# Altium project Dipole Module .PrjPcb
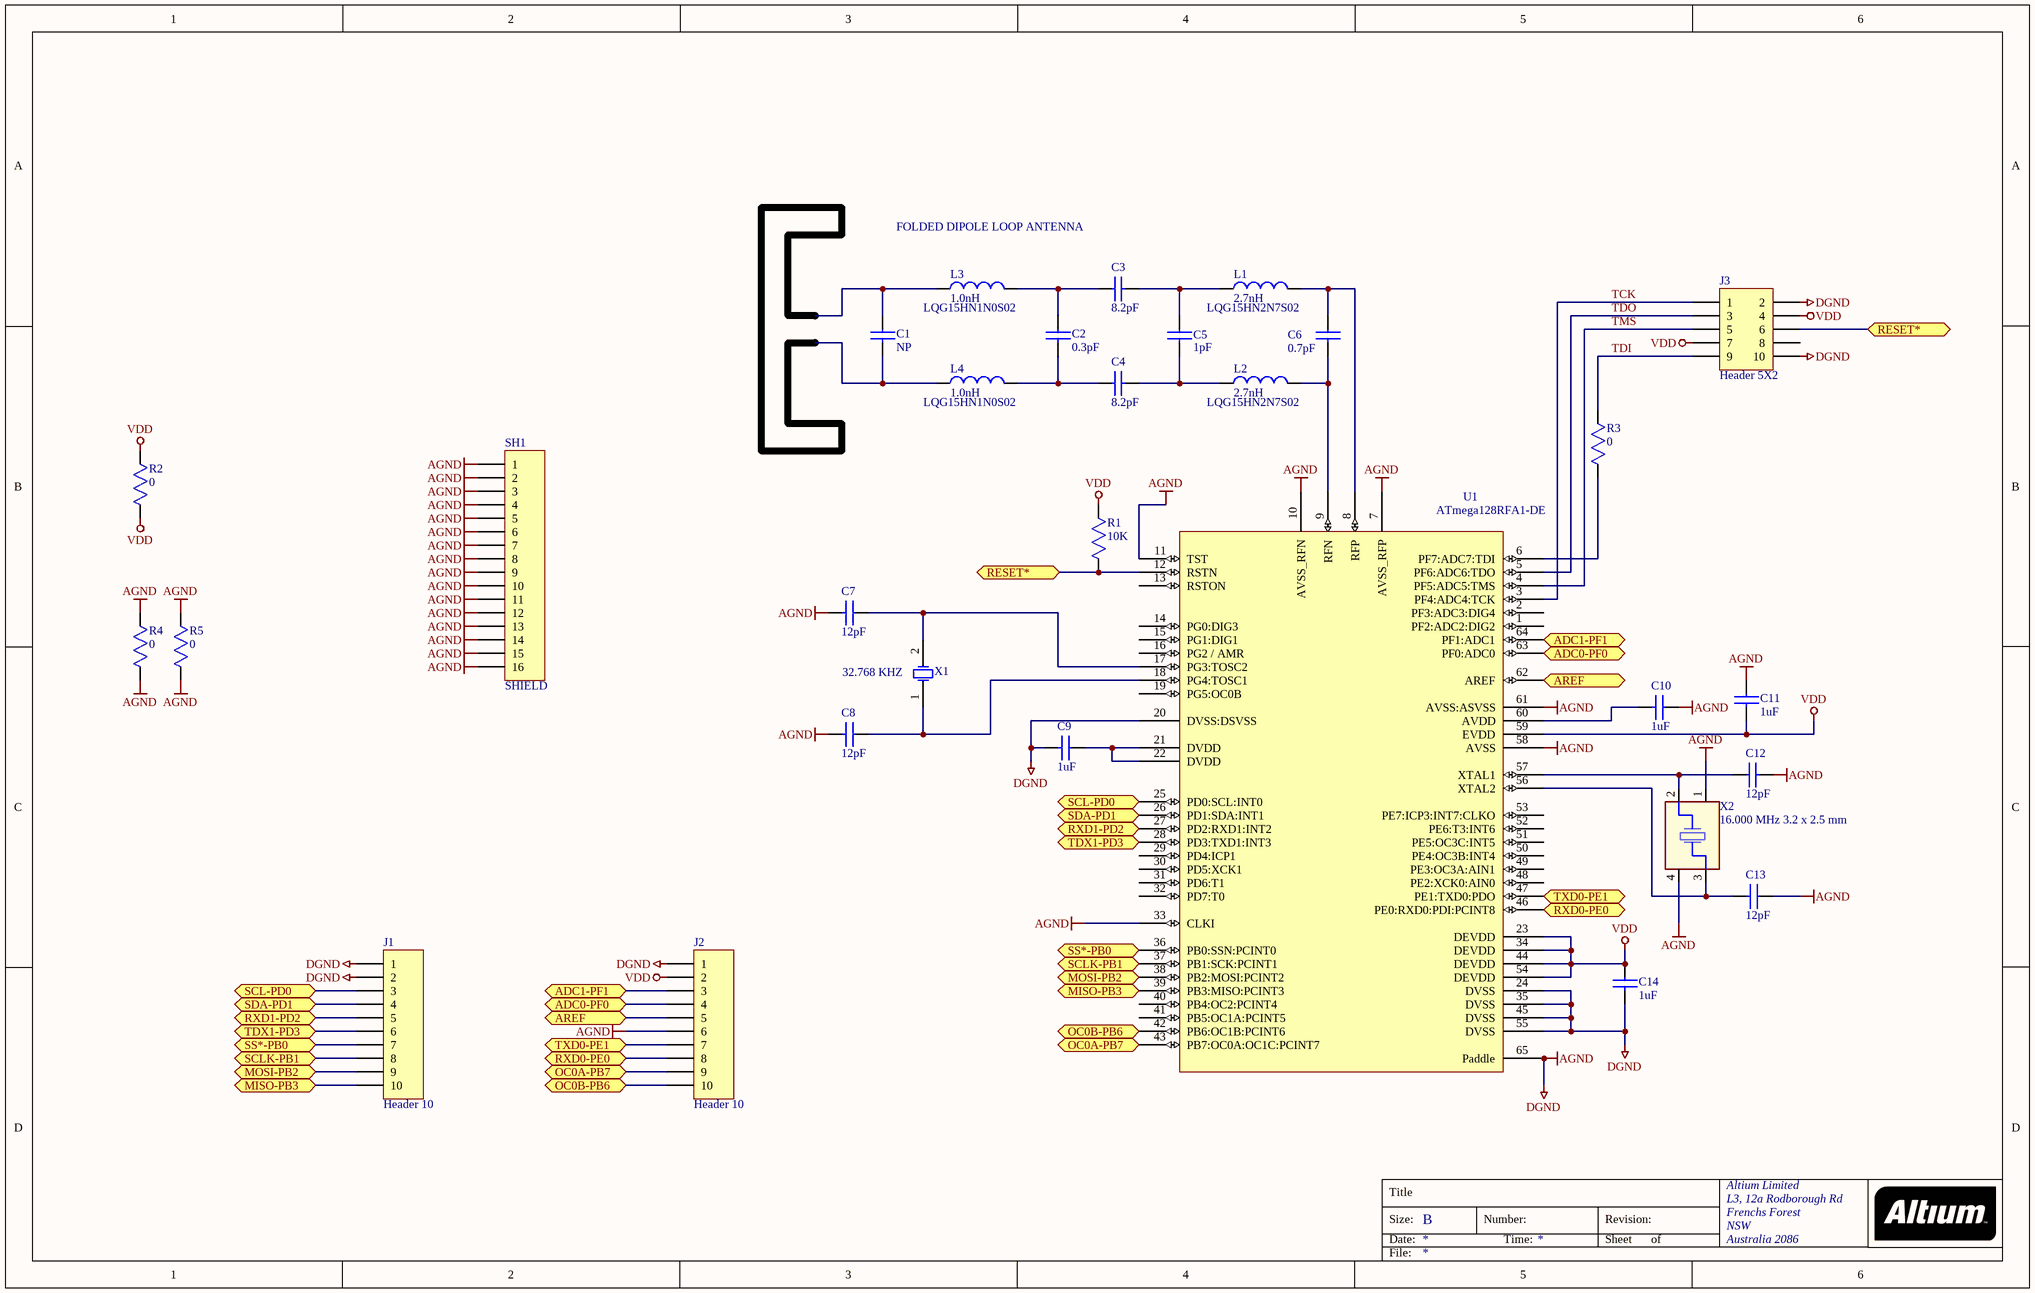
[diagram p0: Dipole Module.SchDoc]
1 sheet, 30 parts. Net scope: flat (ports and power ports of the same name join across sheets).
Board file: Dipole Module.PcbDoc

## Sheet Dipole Module.SchDoc
size B; Organization: Altium Limited; Address1: L3, 12a Rodborough Rd; Address2: Frenchs Forest; Address3: NSW; Address4: Australia 2086

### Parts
C1  NP  [0402]
C2  0.3pF  [0402]
C3  8.2pF  [0402]
C4  8.2pF  [0402]
C5  1pF  [0402-POL]
C6  0.7pF  [0402]
C7  12pF  [0603]
C8  12pF  [0603]
C9  value 1uF  [0603]  (hidden comment: X5R)
C10  value 1uF  [0603]  (hidden comment: X5R)
C11  value 1uF  [0603]  (hidden comment: X5R)
C12  12pF  [0603]
C13  12pF  [0603]
C14  value 1uF  [0603]  (hidden comment: X5R)
J1  Header 10  [HDR1X10]
J2  Header 10  [HDR1X10]
J3  Header 5X2
L1  LQG15HN2N7S02  value 2.7nH  [0402-POL]
L2  LQG15HN2N7S02  value 2.7nH  [0402-POL]
L3  LQG15HN1N0S02  value 1.0nH  [0402-POL]
L4  LQG15HN1N0S02  value 1.0nH  [0402-POL]
R1  value 10K  [0603]  (hidden comment: 0.5)
R2  value 0  [0603]  (hidden comment: 0.5)
R3  value 0  [1206_JUMPER]  (hidden comment: 0.5)
R4  value 0  [0603]  (hidden comment: 0.5)
R5  value 0  [1206_JUMPER]  (hidden comment: 0.5)
SH1  SHIELD  [SHIELD_BMI-S-103_LAIRD]
U1  ATmega128RFA1-DE  [MLF64-M2]
X1  32.768 KHZ  [XTAL32_768KHZ_ABRACON]
X2  16.000 MHz 3.2 x 2.5 mm  [XTAL16MHZKYOCERA]

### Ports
ADC0-PF0, ADC1-PF1, AREF, MISO-PB3, MOSI-PB2, OC0A-PB7, OC0B-PB6, RESET*, RXD0-PE0, RXD1-PD2, SCL-PD0, SCLK-PB1, SDA-PD1, SS*-PB0, TDX1-PD3, TXD0-PE1

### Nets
AGND: C7.2 C8.2 C9.2 C10.1 C11.1 C12.2 C13.1 C14.2 J1.1 J1.2 J2.1 J2.6 J3.2 J3.10 R4.1 R4.2 R5.1 R5.2 SH1.1 SH1.2 SH1.3 SH1.4 SH1.5 SH1.6 SH1.7 SH1.8 SH1.9 SH1.10 SH1.11 SH1.12 SH1.13 SH1.14 SH1.15 SH1.16 U1.7(AVSS_RFP) U1.10(AVSS_RFN) U1.11(TST) U1.20(DVSS:DSVSS) U1.24(DVSS) U1.33(CLKI) U1.35(DVSS) U1.45(DVSS) U1.55(DVSS) U1.58(AVSS) U1.61(AVSS:ASVSS) U1.65(Paddle) X2.1 X2.4  [also labelled DGND]
VDD: C11.2 C14.1 J2.2 J3.4 J3.7 R1.1 R2.1 R2.2 U1.23(DEVDD) U1.34(DEVDD) U1.44(DEVDD) U1.54(DEVDD) U1.59(EVDD)
TCK: J3.1 U1.3(PF4:ADC4:TCK)
TDI: J3.9 R3.1
TDO: J3.3 U1.5(PF6:ADC6:TDO)
TMS: J3.5 U1.4(PF5:ADC5:TMS)
NetC1_1: C1.1 C1.2 L3.1 L4.1
NetC2_1: C2.1 C3.1 L3.2
NetC2_2: C2.2 C4.1 L4.2
NetC3_2: C3.2 C5.1 L1.1
NetC4_2: C4.2 C5.2 L2.1
NetC6_1: C6.1 L1.2 U1.8(RFP)
NetC6_2: C6.2 L2.2 U1.9(RFN)
NetC7_1: C7.1 U1.17(PG3:TOSC2) X1.2(OSC2)
NetC8_1: C8.1 U1.18(PG4:TOSC1) X1.1(OSC1)
NetC9_1: C9.1 U1.21(DVDD) U1.22(DVDD)
NetC10_2: C10.2 U1.60(AVDD)
NetC12_1: C12.1 U1.57(XTAL1) X2.2
NetC13_2: C13.2 U1.56(XTAL2) X2.3
NetJ1_3: J1.3 U1.25(PD0:SCL:INT0) ; port SCL-PD0
NetJ1_4: J1.4 U1.26(PD1:SDA:INT1) ; port SDA-PD1
NetJ1_5: J1.5 U1.27(PD2:RXD1:INT2) ; port RXD1-PD2
NetJ1_6: J1.6 U1.28(PD3:TXD1:INT3) ; port TDX1-PD3
NetJ1_7: J1.7 U1.36(PB0:SSN:PCINT0) ; port SS*-PB0
NetJ1_8: J1.8 U1.37(PB1:SCK:PCINT1) ; port SCLK-PB1
NetJ1_9: J1.9 U1.38(PB2:MOSI:PCINT2) ; port MOSI-PB2
NetJ1_10: J1.10 U1.39(PB3:MISO:PCINT3) ; port MISO-PB3
NetJ2_3: J2.3 U1.64(PF1:ADC1) ; port ADC1-PF1
NetJ2_4: J2.4 U1.63(PF0:ADC0) ; port ADC0-PF0
NetJ2_5: J2.5 U1.62(AREF) ; port AREF
NetJ2_7: J2.7 U1.47(PE1:TXD0:PDO) ; port TXD0-PE1
NetJ2_8: J2.8 U1.46(PE0:RXD0:PDI:PCINT8) ; port RXD0-PE0
NetJ2_9: J2.9 U1.43(PB7:OC0A:OC1C:PCINT7) ; port OC0A-PB7
NetJ2_10: J2.10 U1.42(PB6:OC1B:PCINT6) ; port OC0B-PB6
NetJ3_6: J3.6 R1.2 U1.12(RSTN) ; port RESET*
NetR3_2: R3.2 U1.6(PF7:ADC7:TDI)

Not connected (* = marked no-connect by the designer): J3 8; U1 1(PF2:ADC2:DIG2) 2(PF3:ADC3:DIG4) 13(RSTON) 14(PG0:DIG3) 15(PG1:DIG1) 16(PG2_/_AMR) 19(PG5:OC0B) 29(PD4:ICP1) 30(PD5:XCK1) 31(PD6:T1) 32(PD7:T0) 40(PB4:OC2:PCINT4) 41(PB5:OC1A:PCINT5) 48(PE2:XCK0:AIN0) 49(PE3:OC3A:AIN1) 50(PE4:OC3B:INT4) 51(PE5:OC3C:INT5) 52(PE6:T3:INT6) 53(PE7:ICP3:INT7:CLKO)

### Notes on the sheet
- FOLDED DIPOLE LOOP ANTENNA

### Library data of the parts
C1 = CAP CER NP
C2 = CAP CER 3PF
C3 C4 = CAP CER 82PF
C5 = CAP CER 1PF
C6 = CAP CER 7PF
C7-C14 = CAP CER 15PF
J1 J2 = Header 10: Header, 10-Pin
J3 = Header 5X2: Header, 5-Pin, Dual row
L1 L2 = INDUCTOR SHIELD PWR 27nH: 27nH
L3 = INDUCTOR SHIELD PWR 10nH: 1.0nH
L4 = INDUCTOR SHIELD PWR 10nH: 10nH
R1-R5 = RES .50 OHM 1W 1% 2512 SMD: Manufacturer: Vishay Dale; MPN: WSL2512R5000FEA
SH1 = Header 16H: Header, 16-Pin, Right Angle
U1 = ATmega128RFA1-DE: 802.15.4 compliant AVR transceiver
X1 = XTAL: CRYSTAL 32.768KHZ 12.5PF SMD; MPN: ABS07-32.768KHZ-T; MFG: ABRACON; VENDOR: DIGIKEY; VPN: 535-9542-1-ND
X2 = CRYSTAL 16MHZ 8PF SMD: Manufacturer: Kyocera; Value: CX3225GB16000D0HPQZ1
